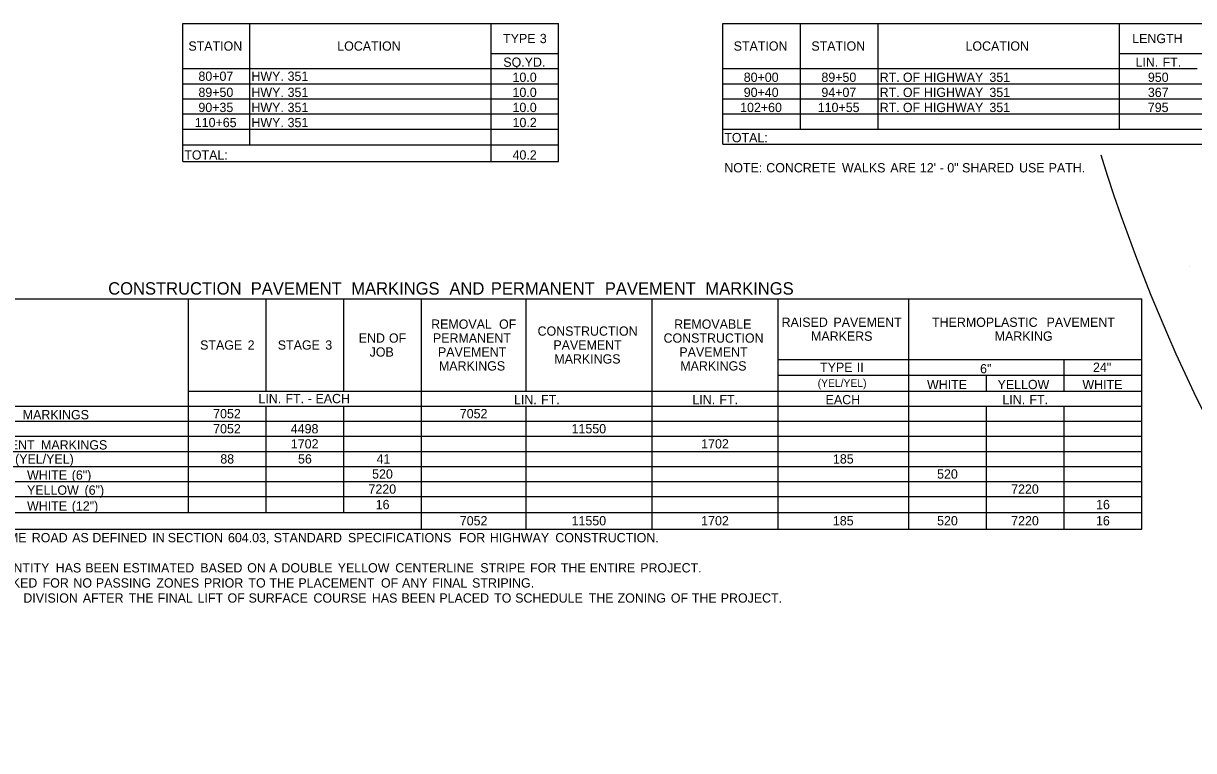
# Model space of a CAD drawing. Extents: x 1197542 to 1207068, y 230488 to 237324.
# Drawn here: x 1198077 to 1198833, y 231758 to 232228 of the extents above; entities that cross this region are included whole.
import ezdxf

# ---------------------------------------------------------------- set-up
doc = ezdxf.new("R2010")
doc.units = 0
doc.layers.add('Default', color=7, linetype='Continuous')
doc.layers.add('R_Proposed Road_Shoulder', color=7, linetype='Continuous')

msp = doc.modelspace()

# ---------------------------------------------------------------- linework, layer by layer
at = {"layer": 'Default'}
for p, q in [((1198180.07, 232227.57), (1198422.85, 232227.57)), ((1198180.07, 232138.36), (1198180.07, 232227.57)), ((1198180.07, 232138.36), (1198180.07, 232227.57)), ((1198223.46, 232149.09), (1198223.46, 232227.57)), ((1198379.46, 232138.36), (1198379.46, 232227.57)), ((1198422.85, 232138.36), (1198422.85, 232227.57)), ((1198422.85, 232208.07), (1198422.85, 232227.57)), ((1198529.08, 232227.57), (1198885.93, 232227.57)), ((1198529.08, 232149.57), (1198529.08, 232227.57)), ((1198529.08, 232149.57), (1198529.08, 232227.57)), ((1198579.29, 232159.32), (1198579.29, 232227.57)), ((1198629.5, 232159.32), (1198629.5, 232227.57)), ((1198785.5, 232159.32), (1198785.5, 232227.57)), ((1198379.46, 232208.07), (1198422.85, 232208.07)), ((1198785.5, 232208.07), (1198885.93, 232208.07)), ((1198180.07, 232198.32), (1198422.85, 232198.32)), ((1198422.85, 232138.36), (1198422.85, 232198.32)), ((1198529.08, 232198.32), (1198835.71, 232198.32)), ((1198785.5, 232198.32), (1198835.71, 232198.32)), ((1198180.07, 232188.57), (1198422.85, 232188.57)), ((1198223.46, 232149.09), (1198223.46, 232188.57)), ((1198379.46, 232138.36), (1198379.46, 232188.57)), ((1198529.08, 232188.57), (1198885.93, 232188.57)), ((1198180.07, 232178.82), (1198422.85, 232178.82)), ((1198529.08, 232178.82), (1198885.93, 232178.82)), ((1198180.07, 232169.07), (1198422.85, 232169.07)), ((1198529.08, 232169.07), (1198885.93, 232169.07)), ((1198579.29, 232159.32), (1198579.29, 232169.07)), ((1198629.5, 232159.32), (1198629.5, 232169.07)), ((1198785.5, 232159.32), (1198785.5, 232169.07)), ((1198180.07, 232159.32), (1198422.85, 232159.32)), ((1198529.08, 232159.32), (1198885.93, 232159.32)), ((1198180.07, 232149.09), (1198422.85, 232149.09)), ((1198529.08, 232149.57), (1198885.93, 232149.57)), ((1198180.07, 232138.36), (1198422.85, 232138.36)), ((1198830.8, 232070.3), (1198830.8, 232070.3)), ((1197916.07, 232049.46), (1198799.9, 232049.46)), ((1198183.7, 231911.5), (1198183.7, 232049.46)), ((1198233.92, 231989.99), (1198233.92, 232049.46)), ((1198284.13, 231989.99), (1198284.13, 232049.46)), ((1198334.34, 231900.77), (1198334.34, 232049.46)), ((1198402.1, 231989.99), (1198402.1, 232049.46)), ((1198483.52, 231900.77), (1198483.52, 232049.46)), ((1198564.93, 231900.77), (1198564.93, 232049.46)), ((1198649.27, 231900.77), (1198649.27, 232049.46)), ((1198799.9, 231980.24), (1198799.9, 232049.46)), ((1198564.93, 232010.46), (1198799.9, 232010.46)), ((1198749.69, 231989.99), (1198749.69, 232010.46)), ((1198564.93, 232000.22), (1198799.9, 232000.22)), ((1198699.48, 231989.99), (1198699.48, 232000.22)), ((1198749.69, 232000.22), (1198799.9, 232000.22)), ((1198749.69, 231989.99), (1198749.69, 232000.22)), ((1198183.7, 231989.99), (1198799.9, 231989.99)), ((1198649.27, 231900.77), (1198649.27, 231989.99)), ((1197916.07, 231980.24), (1198799.9, 231980.24)), ((1198183.7, 231911.5), (1198183.7, 231980.24)), ((1198233.92, 231911.5), (1198233.92, 231980.24)), ((1198233.92, 231911.5), (1198233.92, 231980.24)), ((1198284.13, 231911.5), (1198284.13, 231980.24)), ((1198284.13, 231911.5), (1198284.13, 231980.24)), ((1198334.34, 231900.77), (1198334.34, 231980.24)), ((1198402.1, 231900.77), (1198402.1, 231980.24)), ((1198402.1, 231900.77), (1198402.1, 231980.24)), ((1198483.52, 231900.77), (1198483.52, 231980.24)), ((1198564.93, 231900.77), (1198564.93, 231980.24)), ((1198699.48, 231900.77), (1198699.48, 231980.24)), ((1198699.48, 231900.77), (1198699.48, 231980.24)), ((1198749.69, 231900.77), (1198749.69, 231980.24)), ((1198749.69, 231900.77), (1198749.69, 231980.24)), ((1198799.9, 231900.77), (1198799.9, 231980.24)), ((1197916.07, 231970.49), (1198799.9, 231970.49)), ((1197916.07, 231960.74), (1198799.9, 231960.74)), ((1197916.07, 231950.99), (1198799.9, 231950.99)), ((1197916.07, 231941.24), (1198799.9, 231941.24)), ((1197916.07, 231931.49), (1198799.9, 231931.49)), ((1197916.07, 231921.74), (1198799.9, 231921.74)), ((1197916.07, 231911.5), (1198799.9, 231911.5)), ((1197916.07, 231911.5), (1198334.34, 231911.5)), ((1197916.07, 231900.77), (1198799.9, 231900.77))]:
    msp.add_line(p, q, dxfattribs=at)
at = {"layer": 'R_Proposed Road_Shoulder'}
msp.add_arc((1199867.71, 232482.58), 1145.92, 197.25666, 219.24757, dxfattribs=at)

# ---------------------------------------------------------------- texts
at = {"layer": 'Default'}
for s, height, p in [('TYPE', 6, (1198387.1, 232214.82)), (' 3', 6, (1198408.58, 232214.82)), ('LENGTH', 6, (1198793.7, 232214.82)), ('STATION', 6, (1198183.71, 232209.95)), ('LOCATION', 6, (1198279.91, 232209.95)), ('STATION', 6, (1198536.12, 232209.95)), ('STATION', 6, (1198586.33, 232209.95)), ('LOCATION', 6, (1198685.95, 232209.95)), ('SQ.YD.', 6, (1198387.23, 232199.52)), ('LIN.', 6, (1198795.82, 232199.52)), (' FT.', 6, (1198811.07, 232199.52)), ('80+07', 6, (1198190.19, 232190.45)), ('HWY.', 6, (1198224.44, 232190.45)), (' 351', 6, (1198245.59, 232190.45)), ('10.0', 6, (1198393.2, 232189.77)), ('80+00', 6, (1198542.62, 232189.77)), ('89+50', 6, (1198592.83, 232189.77)), ('RT.', 6, (1198630.48, 232189.77)), (' OF', 6, (1198643.25, 232189.77)), (' HIGHWAY', 6, (1198656.84, 232189.77)), (' 351', 6, (1198699.16, 232189.77)), ('950', 6, (1198803.82, 232189.77)), ('89+50', 6, (1198190.2, 232180.02)), ('HWY.', 6, (1198224.44, 232180.02)), (' 351', 6, (1198245.59, 232180.02)), ('10.0', 6, (1198393.2, 232180.02)), ('90+40', 6, (1198542.62, 232180.02)), ('94+07', 6, (1198592.82, 232180.02)), ('RT.', 6, (1198630.48, 232180.02)), (' OF', 6, (1198643.25, 232180.02)), (' HIGHWAY', 6, (1198656.84, 232180.02)), (' 351', 6, (1198699.16, 232180.02)), ('367', 6, (1198803.81, 232180.02)), ('90+35', 6, (1198190.17, 232170.27)), ('HWY.', 6, (1198224.44, 232170.27)), (' 351', 6, (1198245.59, 232170.27)), ('10.0', 6, (1198393.2, 232170.27)), ('102+60', 6, (1198540.29, 232170.27)), ('110+55', 6, (1198590.46, 232170.27)), ('RT.', 6, (1198630.48, 232170.27)), (' OF', 6, (1198643.25, 232170.27)), (' HIGHWAY', 6, (1198656.84, 232170.27)), (' 351', 6, (1198699.16, 232170.27)), ('795', 6, (1198803.78, 232170.27)), ('110+65', 6, (1198187.84, 232160.52)), ('HWY.', 6, (1198224.44, 232160.52)), (' 351', 6, (1198245.59, 232160.52)), ('10.2', 6, (1198393.22, 232160.52)), ('TOTAL:', 6, (1198530.05, 232150.77)), ('TOTAL:', 6, (1198181.05, 232139.56)), ('40.2', 6, (1198393.21, 232139.56)), ('NOTE:', 6, (1198530.05, 232131.27)), (' CONCRETE', 6, (1198554.94, 232131.27)), (' WALKS', 6, (1198603.87, 232131.27)), (' ARE', 6, (1198635.11, 232131.27)), (" 12'", 6, (1198654.23, 232131.27)), (' 0"', 6, (1198671.94, 232131.27)), (' SHARED', 6, (1198681.51, 232131.27)), (' USE', 6, (1198718.33, 232131.27)), (' PATH.', 6, (1198737.45, 232131.27)), (' -', 6, (1198667.08, 232131.27)), ('CONSTRUCTION', 8, (1198131.86, 232052.29)), (' PAVEMENT', 8, (1198221.01, 232052.29)), (' MARKINGS', 8, (1198286, 232052.29)), (' AND', 8, (1198349.41, 232052.29)), (' PERMANENT', 8, (1198376.18, 232052.29)), (' PAVEMENT', 8, (1198449.86, 232052.29)), (' MARKINGS', 8, (1198514.85, 232052.29)), ('REMOVAL', 6, (1198340.59, 232030.22)), (' OF', 6, (1198382.27, 232030.22)), ('CONSTRUCTION', 6, (1198409.38, 232025.72)), ('REMOVABLE', 6, (1198497.64, 232030.22)), ('RAISED', 6, (1198567.09, 232031.46)), (' PAVEMENT', 6, (1198598.36, 232031.46)), ('THERMOPLASTIC', 6, (1198664.33, 232031.46)), (' PAVEMENT', 6, (1198736.1, 232031.46)), ('STAGE', 6, (1198191.29, 232016.72)), (' 2', 6, (1198219.76, 232016.72)), ('STAGE', 6, (1198241.47, 232016.72)), (' 3', 6, (1198269.94, 232016.72)), ('END', 6, (1198293.8, 232021.22)), (' OF', 6, (1198311.09, 232021.22)), ('PERMANENT', 6, (1198341.76, 232021.22)), ('PAVEMENT', 6, (1198419.6, 232016.72)), ('CONSTRUCTION', 6, (1198490.79, 232021.22)), ('MARKERS', 6, (1198586.11, 232022.46)), ('MARKING', 6, (1198704.81, 232022.46)), ('JOB', 6, (1198300.82, 232012.22)), ('PAVEMENT', 6, (1198345.01, 232012.22)), ('PAVEMENT', 6, (1198501.01, 232012.22)), ('MARKINGS', 6, (1198345.6, 232003.22)), ('MARKINGS', 6, (1198420.19, 232007.72)), ('MARKINGS', 6, (1198501.6, 232003.22)), ('TYPE', 6, (1198591.97, 232002.34)), (' II', 6, (1198613.46, 232002.34)), ('24"', 6, (1198768.36, 232002.34)), ('6"', 6, (1198695.37, 232001.42)), ('(YEL/YEL)', 5, (1198590.39, 231992.61)), ('WHITE', 6, (1198661.07, 231991.19)), ('YELLOW', 6, (1198706.66, 231991.19)), ('WHITE', 6, (1198761.5, 231991.19)), ('LIN.', 6, (1198228.98, 231982.11)), (' FT.', 6, (1198244.24, 231982.11)), (' EACH', 6, (1198263.62, 231982.11)), ('LIN.', 6, (1198394.14, 231981.44)), (' FT.', 6, (1198409.39, 231981.44)), ('LIN.', 6, (1198509.43, 231981.44)), (' FT.', 6, (1198524.69, 231981.44)), ('EACH', 6, (1198595.54, 231981.44)), ('LIN.', 6, (1198709.79, 231981.44)), (' FT.', 6, (1198725.05, 231981.44)), (' MARKINGS', 6, (1198074.41, 231971.69)), ('7052', 6, (1198199.71, 231972.36)), (' -', 6, (1198258.56, 231982.11)), ('7052', 6, (1198359.12, 231972.36)), ('7052', 6, (1198199.71, 231962.61)), ('4498', 6, (1198249.89, 231962.61)), ('11550', 6, (1198431.36, 231962.61)), (' PAVEMENT', 6, (1198037.95, 231952.19)), (' MARKINGS', 6, (1198086.24, 231952.19)), ('1702', 6, (1198249.92, 231952.86)), ('1702', 6, (1198515.12, 231952.86)), (' (YEL/YEL)', 6, (1198069.46, 231943.11)), ('88', 6, (1198204.33, 231943.11)), ('56', 6, (1198254.55, 231943.11)), ('41', 6, (1198305.34, 231943.11)), ('185', 6, (1198600.27, 231943.11)), (' WHITE', 6, (1198077.19, 231932.69)), (' (6")', 6, (1198106.08, 231932.69)), ('520', 6, (1198302.44, 231933.36)), ('520', 6, (1198667.58, 231933.36)), (' YELLOW', 6, (1198077.19, 231922.94)), (' (6")', 6, (1198114.36, 231922.94)), ('7220', 6, (1198300.11, 231923.61)), ('7220', 6, (1198715.46, 231923.61)), (' WHITE', 6, (1198077.19, 231912.7)), (' (12")', 6, (1198106.08, 231912.7)), ('16', 6, (1198304.76, 231913.62)), ('16', 6, (1198770.33, 231913.62)), ('7052', 6, (1198359.11, 231903.14)), ('11550', 6, (1198431.36, 231903.14)), ('1702', 6, (1198515.11, 231903.14)), ('185', 6, (1198600.23, 231903.14)), ('520', 6, (1198667.59, 231903.14)), ('7220', 6, (1198715.47, 231903.14)), ('16', 6, (1198770.28, 231903.14)), (' VOLUME', 6, (1198042.99, 231892.22)), (' ROAD', 6, (1198080.27, 231892.22)), (' AS', 6, (1198106.37, 231892.22)), (' DEFINED', 6, (1198119.45, 231892.22)), (' IN', 6, (1198158.13, 231892.22)), (' SECTION', 6, (1198168.15, 231892.22)), (' 604.03,', 6, (1198207.06, 231892.22)), (' STANDARD', 6, (1198236.6, 231892.22)), (' SPECIFICATIONS', 6, (1198284.6, 231892.22)), (' FOR', 6, (1198356.37, 231892.22)), (' HIGHWAY', 6, (1198376.28, 231892.22)), (' CONSTRUCTION.', 6, (1198418.6, 231892.22)), (' QUANTITY', 6, (1198051.04, 231872.72)), (' HAS', 6, (1198095.7, 231872.72)), (' BEEN', 6, (1198114.83, 231872.72)), (' ESTIMATED', 6, (1198139.3, 231872.72)), (' BASED', 6, (1198189.16, 231872.72)), (' ON', 6, (1198219.47, 231872.72)), (' A', 6, (1198233.69, 231872.72)), (' DOUBLE', 6, (1198241.62, 231872.72)), (' YELLOW', 6, (1198277.98, 231872.72)), (' CENTERLINE', 6, (1198315.15, 231872.72)), (' STRIPE', 6, (1198370.14, 231872.72)), (' FOR', 6, (1198402.3, 231872.72)), (' THE', 6, (1198422.21, 231872.72)), (' ENTIRE', 6, (1198440.86, 231872.72)), (' PROJECT.', 6, (1198473.49, 231872.72)), (' MARKED', 6, (1198049.49, 231862.97)), (' FOR', 6, (1198087.24, 231862.97)), (' NO', 6, (1198107.15, 231862.97)), (' PASSING', 6, (1198121.68, 231862.97)), (' ZONES', 6, (1198160.76, 231862.97)), (' PRIOR', 6, (1198191.53, 231862.97)), (' TO', 6, (1198220.29, 231862.97)), (' THE', 6, (1198233.89, 231862.97)), (' PLACEMENT', 6, (1198252.54, 231862.97)), (' OF', 6, (1198305.94, 231862.97)), (' ANY', 6, (1198319.53, 231862.97)), (' FINAL', 6, (1198339.04, 231862.97)), (' STRIPING.', 6, (1198364.82, 231862.97)), (' DIVISION', 6, (1198074.8, 231853.22)), (' AFTER', 6, (1198113.24, 231853.22)), (' THE', 6, (1198142.94, 231853.22)), (' FINAL', 6, (1198161.59, 231853.22)), (' LIFT', 6, (1198187.38, 231853.22)), (' OF', 6, (1198206.77, 231853.22)), (' SURFACE', 6, (1198220.36, 231853.22)), (' COURSE', 6, (1198262.3, 231853.22)), (' HAS', 6, (1198300.05, 231853.22)), (' BEEN', 6, (1198319.18, 231853.22)), (' PLACED', 6, (1198343.66, 231853.22)), (' TO', 6, (1198379.09, 231853.22)), (' SCHEDULE', 6, (1198392.68, 231853.22)), (' THE', 6, (1198440.22, 231853.22)), (' ZONING', 6, (1198458.87, 231853.22)), (' OF', 6, (1198493.28, 231853.22)), (' THE', 6, (1198506.86, 231853.22)), (' PROJECT.', 6, (1198525.51, 231853.22))]:
    msp.add_text(s, height=height, dxfattribs=at).set_placement(p)

doc.saveas('drawing.dxf')
